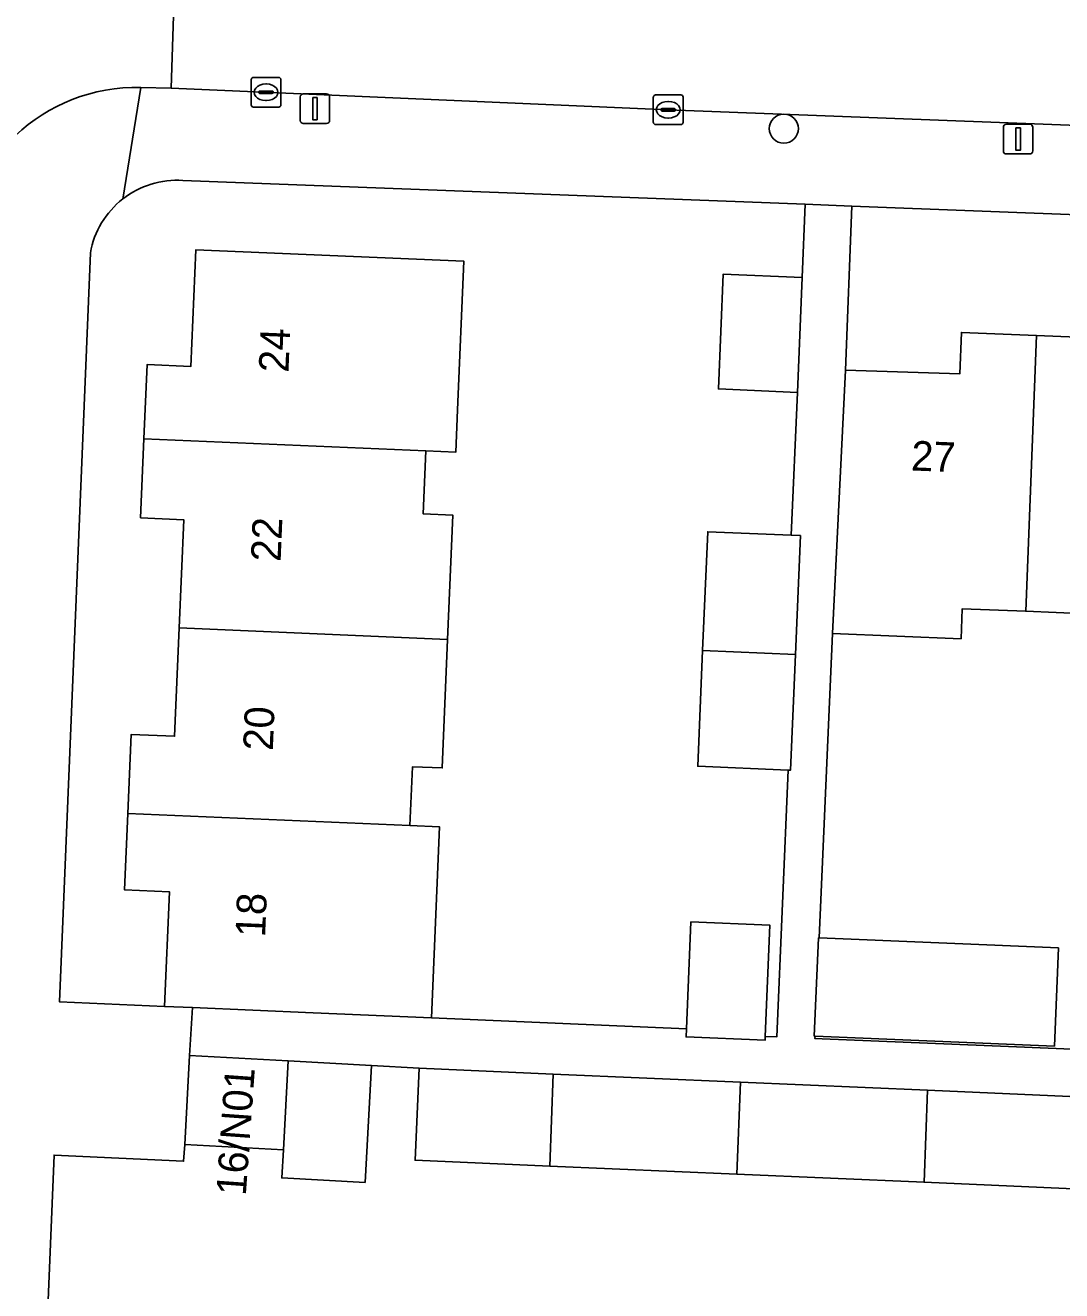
# Model space of a CAD drawing. Extents: x 160732 to 162107, y 387428 to 388479.
# Drawn here: x 161267.54 to 161302.41, y 387574.75 to 387617.33 of the extents above; entities that cross this region are included whole.
import ezdxf

# ---------------------------------------------------------------- set-up
doc = ezdxf.new("R2010")
doc.units = 0
for name, color, linetype in [('IMGEO_Boom', 7, 'Continuous'), ('IMGEO_Erf', 7, 'Continuous'), ('IMGEO_Kolk', 7, 'Continuous'), ('IMGEO_Lichtmast', 7, 'Continuous'), ('IMGEO_Pand', 7, 'Continuous'), ('IMGEO_Pand_nummerreeks', 7, 'Continuous'), ('IMGEO_Rijbaan_lokaal_open', 7, 'Continuous'), ('IMGEO_Voetpad_open', 7, 'Continuous')]:
    doc.layers.add(name, color=color, linetype=linetype)

msp = doc.modelspace()

# ---------------------------------------------------------------- linework, layer by layer
at = {"layer": 'IMGEO_Boom'}
msp.add_circle((161293.062, 387613.849), 0.489, dxfattribs=at)
at = {"layer": 'IMGEO_Erf'}
for points in [[(161293.213, 387592.265), (161290.164, 387592.396), (161290.33, 387596.291), (161290.502, 387600.289), (161293.313, 387600.169), (161293.518, 387604.977), (161290.86, 387605.09), (161291.025, 387608.958), (161293.683, 387608.845), (161293.778, 387611.304), (161272.842, 387612.109)], [(161350.027, 387609.14), (161295.346, 387611.244), (161295.134, 387605.725), (161298.979, 387605.598), (161299.035, 387606.991), (161301.569, 387606.89), (161304.303, 387606.782)], [(161269.729, 387609.67), (161268.695, 387584.47), (161272.229, 387584.319), (161272.394, 387588.17), (161270.882, 387588.235), (161270.992, 387590.81), (161271.106, 387593.468), (161272.562, 387593.406), (161272.718, 387597.051), (161272.873, 387600.693), (161271.416, 387600.756), (161271.53, 387603.417), (161271.636, 387605.91), (161273.114, 387605.847), (161273.282, 387609.775), (161282.296, 387609.389), (161282.082, 387604.394), (161282.021, 387602.964), (161281.021, 387603.007), (161280.93, 387600.886), (161281.93, 387600.843), (161281.751, 387596.661), (161281.567, 387592.341), (161280.568, 387592.383), (161280.483, 387590.4), (161281.482, 387590.357), (161281.207, 387583.935), (161289.783, 387583.569), (161289.936, 387587.161), (161292.594, 387587.048), (161292.435, 387583.31), (161292.825, 387583.294), (161293.213, 387592.265)], [(161303.248, 387597.53), (161301.2, 387597.613), (161299.067, 387597.699), (161299.026, 387596.69), (161294.699, 387596.865), (161294.256, 387586.623), (161302.303, 387586.286), (161302.165, 387582.982), (161294.114, 387583.32), (161294.11, 387583.238), (161294.347, 387583.228), (161300.618, 387582.965), (161303.023, 387582.864)], [(161304.079, 387578.129), (161297.782, 387578.401), (161291.483, 387578.673), (161285.186, 387578.945), (161280.657, 387579.141), (161280.791, 387582.236), (161279.188, 387582.334), (161278.975, 387578.398), (161276.171, 387578.55), (161276.222, 387579.491), (161272.905, 387579.671), (161272.863, 387579.112), (161268.51, 387579.316), (161267.578, 387556.812)]]:
    msp.add_lwpolyline(points, dxfattribs=at)
for centre, radius, start, end in [((161272.657, 387609.136), 2.979, 86.4334, 128.0388), ((161272.653, 387609.143), 2.972, 128.0717, 169.7779)]:
    msp.add_arc(centre, radius, start, end, dxfattribs=at)
at = {"layer": 'IMGEO_Kolk'}
for p, q in [((161275.215, 387615.572), (161276.067, 387615.572)), ((161275.14, 387614.646), (161275.14, 387615.498)), ((161275.442, 387615.115), (161275.84, 387615.115)), ((161275.628, 387615.352), (161275.653, 387615.352)), ((161276.141, 387615.498), (161276.141, 387614.646)), ((161275.399, 387615.066), (161275.399, 387615.078)), ((161275.837, 387615.029), (161275.439, 387615.029)), ((161275.651, 387614.792), (161275.626, 387614.792)), ((161275.883, 387615.078), (161275.883, 387615.066)), ((161288.671, 387614.058), (161288.671, 387614.91)), ((161288.746, 387614.984), (161289.598, 387614.984)), ((161289.159, 387614.764), (161289.184, 387614.764)), ((161289.672, 387614.91), (161289.672, 387614.058)), ((161276.067, 387614.572), (161275.215, 387614.572)), ((161288.93, 387614.478), (161288.93, 387614.49)), ((161289.368, 387614.441), (161288.97, 387614.441)), ((161288.973, 387614.527), (161289.371, 387614.527)), ((161289.414, 387614.49), (161289.414, 387614.478)), ((161289.598, 387613.984), (161288.746, 387613.984)), ((161289.182, 387614.204), (161289.157, 387614.204))]:
    msp.add_line(p, q, dxfattribs=at)
for points in [[(161275.215, 387615.572), (161276.067, 387615.572)], [(161275.14, 387614.646), (161275.14, 387615.498)], [(161276.141, 387615.498), (161276.141, 387614.646)], [(161288.671, 387614.058), (161288.671, 387614.91)], [(161288.746, 387614.984), (161289.598, 387614.984)], [(161289.672, 387614.91), (161289.672, 387614.058)], [(161276.067, 387614.572), (161275.215, 387614.572)], [(161289.598, 387613.984), (161288.746, 387613.984)]]:
    msp.add_lwpolyline(points, dxfattribs=at)
for centre, radius, start, end in [((161275.217, 387615.496), 0.0765, 91.552, 178.448), ((161275.217, 387615.496), 0.0765, 91.552, 178.448), ((161276.065, 387615.496), 0.0765, 1.552, 88.448), ((161276.065, 387615.496), 0.0765, 1.552, 88.448), ((161275.439, 387615.075), 0.0403, 85.8775, 175.7526), ((161275.844, 387615.077), 0.0386, 1.7309, 96.639), ((161275.436, 387615.065), 0.0366, 178.938, 274.7102), ((161275.84, 387615.072), 0.043, 264.8664, 352.4533), ((161288.748, 387614.908), 0.0765, 91.552, 178.448), ((161288.748, 387614.908), 0.0765, 91.552, 178.448), ((161289.596, 387614.908), 0.0765, 1.552, 88.448), ((161289.596, 387614.908), 0.0765, 1.552, 88.448), ((161275.217, 387614.648), 0.0765, 181.552, 268.448), ((161275.217, 387614.648), 0.0765, 181.552, 268.448), ((161276.065, 387614.648), 0.0765, 271.552, 358.448), ((161276.065, 387614.648), 0.0765, 271.552, 358.448), ((161288.97, 387614.487), 0.0403, 85.8775, 175.7526), ((161288.967, 387614.477), 0.0366, 178.938, 274.7102), ((161289.371, 387614.484), 0.043, 264.8664, 352.4533), ((161289.375, 387614.489), 0.0386, 1.7309, 96.639), ((161288.748, 387614.06), 0.0765, 181.552, 268.448), ((161288.748, 387614.06), 0.0765, 181.552, 268.448), ((161289.596, 387614.06), 0.0765, 271.552, 358.448), ((161289.596, 387614.06), 0.0765, 271.552, 358.448)]:
    msp.add_arc(centre, radius, start, end, dxfattribs=at)
for centre, major_axis, ratio, start_param, end_param in [((161275.627, 387615.072), (-0.387, 0.002), 0.722429, 4.712389, 7.853982), ((161275.652, 387615.072), (-0.39, 0.002), 0.717154, 1.570796, 4.712389), ((161289.158, 387614.484), (-0.387, 0.002), 0.722429, 4.712389, 7.853982), ((161289.183, 387614.484), (-0.39, 0.002), 0.717154, 1.570796, 4.712389)]:
    msp.add_ellipse(centre, major_axis=major_axis, ratio=ratio, start_param=start_param, end_param=end_param, dxfattribs=at)
at = {"layer": 'IMGEO_Lichtmast'}
for p, q in [((161276.789, 387614.121), (161276.789, 387614.921)), ((161276.789, 387614.921), (161276.789, 387614.121)), ((161276.889, 387615.021), (161277.679, 387615.021)), ((161277.679, 387615.021), (161276.889, 387615.021)), ((161277.779, 387614.921), (161277.779, 387614.121)), ((161277.779, 387614.121), (161277.779, 387614.921)), ((161277.679, 387614.021), (161276.889, 387614.021)), ((161276.889, 387614.021), (161277.679, 387614.021)), ((161300.45, 387613.099), (161300.45, 387613.899)), ((161300.45, 387613.899), (161300.45, 387613.099)), ((161300.55, 387613.999), (161301.34, 387613.999)), ((161301.34, 387613.999), (161300.55, 387613.999)), ((161301.44, 387613.899), (161301.44, 387613.099)), ((161301.44, 387613.099), (161301.44, 387613.899)), ((161301.34, 387612.999), (161300.55, 387612.999)), ((161300.55, 387612.999), (161301.34, 387612.999))]:
    msp.add_line(p, q, dxfattribs=at)
for points in [[(161277.209, 387614.896), (161277.359, 387614.896), (161277.359, 387614.146), (161277.209, 387614.146), (161277.209, 387614.896)], [(161300.87, 387613.874), (161301.02, 387613.874), (161301.02, 387613.124), (161300.87, 387613.124), (161300.87, 387613.874)]]:
    msp.add_lwpolyline(points, dxfattribs=at)
for centre, start, end in [((161276.889, 387614.921), 90, 180), ((161276.889, 387614.921), 90, 180), ((161277.679, 387614.921), 0, 90), ((161277.679, 387614.921), 360, 90), ((161276.889, 387614.121), 180, 270), ((161276.889, 387614.121), 180, 270), ((161277.679, 387614.121), 270, 0), ((161277.679, 387614.121), 270, 0), ((161300.55, 387613.899), 90, 180), ((161300.55, 387613.899), 90, 180), ((161301.34, 387613.899), 0, 90), ((161301.34, 387613.899), 360, 90), ((161300.55, 387613.099), 180, 270), ((161300.55, 387613.099), 180, 270), ((161301.34, 387613.099), 270, 0), ((161301.34, 387613.099), 270, 0)]:
    msp.add_arc(centre, 0.1, start, end, dxfattribs=at)
at = {"layer": 'IMGEO_Pand'}
for points in [[(161282.296, 387609.389), (161273.282, 387609.775), (161273.114, 387605.847), (161271.636, 387605.91), (161271.53, 387603.417), (161281.021, 387603.007), (161282.021, 387602.964), (161282.082, 387604.394)], [(161293.683, 387608.845), (161291.025, 387608.958), (161290.86, 387605.09), (161293.518, 387604.977)], [(161301.569, 387606.89), (161299.035, 387606.991), (161298.979, 387605.598), (161295.134, 387605.725), (161294.889, 387600.732), (161294.699, 387596.865), (161299.026, 387596.69), (161299.067, 387597.699), (161301.2, 387597.613)], [(161307.807, 387605.189), (161304.245, 387605.331), (161304.303, 387606.782), (161301.569, 387606.89), (161301.2, 387597.613), (161303.248, 387597.53), (161303.206, 387596.519), (161307.455, 387596.343)], [(161281.021, 387603.007), (161271.53, 387603.417), (161271.416, 387600.756), (161272.873, 387600.693), (161272.718, 387597.051), (161281.751, 387596.661), (161281.93, 387600.843), (161280.93, 387600.886)], [(161293.313, 387600.169), (161290.502, 387600.289), (161290.33, 387596.291), (161293.45, 387596.156), (161293.621, 387600.156)], [(161281.751, 387596.661), (161272.718, 387597.051), (161272.562, 387593.406), (161271.106, 387593.468), (161270.992, 387590.81), (161280.483, 387590.4), (161280.568, 387592.383), (161281.567, 387592.341)], [(161293.45, 387596.156), (161290.33, 387596.291), (161290.164, 387592.396), (161293.213, 387592.265), (161293.283, 387592.262)], [(161281.482, 387590.357), (161280.483, 387590.4), (161270.992, 387590.81), (161270.882, 387588.235), (161272.394, 387588.17), (161272.229, 387584.319), (161273.16, 387584.279), (161277.225, 387584.105), (161281.207, 387583.935)], [(161292.594, 387587.048), (161289.936, 387587.161), (161289.783, 387583.569), (161289.771, 387583.293), (161292.429, 387583.18), (161292.435, 387583.31)], [(161294.256, 387586.623), (161294.224, 387586.624), (161294.085, 387583.321), (161294.114, 387583.32), (161302.165, 387582.982), (161302.303, 387586.286)], [(161273.067, 387582.666), (161272.905, 387579.671), (161276.222, 387579.491), (161276.384, 387582.486)], [(161276.222, 387579.491), (161276.171, 387578.55), (161278.975, 387578.398), (161279.188, 387582.334), (161276.384, 387582.486)], [(161285.302, 387582.042), (161280.791, 387582.236), (161280.657, 387579.141), (161285.186, 387578.945)], [(161291.6, 387581.769), (161285.302, 387582.042), (161285.186, 387578.945), (161291.483, 387578.673)], [(161297.898, 387581.497), (161291.6, 387581.769), (161291.483, 387578.673), (161297.782, 387578.401)], [(161304.196, 387581.225), (161297.898, 387581.497), (161297.782, 387578.401), (161304.079, 387578.129)]]:
    msp.add_lwpolyline(points, close=True, dxfattribs=at)
at = {"layer": 'IMGEO_Rijbaan_lokaal_open'}
msp.add_lwpolyline([(161271.428, 387615.232), (161272.446, 387615.211), (161272.605, 387620.102)], dxfattribs=at)
msp.add_lwpolyline([(161273.653, 387620.056), (161272.605, 387620.102), (161272.446, 387615.211), (161289.172, 387614.484), (161312.936, 387613.577), (161343.203, 387612.394), (161343.386, 387617.292)], close=True, dxfattribs=at)
msp.add_arc((161271.275, 387609.313), 5.921, 88.5203, 178.1993, dxfattribs=at)
at = {"layer": 'IMGEO_Voetpad_open'}
for points in [[(161422.811, 387609.126), (161411.375, 387609.658), (161407.95, 387609.79), (161356.144, 387611.896), (161356.112, 387610.696), (161347.841, 387611.016), (161347.913, 387612.202), (161346.661, 387612.253), (161343.203, 387612.394), (161312.936, 387613.577), (161289.172, 387614.484), (161272.446, 387615.211), (161271.428, 387615.232), (161270.821, 387611.482)], [(161270.821, 387611.482), (161271.428, 387615.232)], [(161272.842, 387612.109), (161293.778, 387611.304), (161295.346, 387611.244), (161350.027, 387609.14), (161354.703, 387608.945), (161354.697, 387608.799), (161396.894, 387607.128), (161398.295, 387607.073), (161409.384, 387606.634), (161415.333, 387606.399), (161420.803, 387606.202)], [(161303.023, 387582.864), (161300.618, 387582.965), (161294.347, 387583.228), (161294.11, 387583.238), (161294.114, 387583.32), (161294.085, 387583.321), (161294.224, 387586.624), (161294.256, 387586.623), (161294.699, 387596.865), (161294.889, 387600.732), (161295.134, 387605.725), (161295.346, 387611.244), (161293.778, 387611.304), (161293.683, 387608.845), (161293.518, 387604.977), (161293.313, 387600.169), (161293.621, 387600.156), (161293.45, 387596.156), (161293.283, 387592.262), (161293.213, 387592.265), (161292.825, 387583.294), (161292.435, 387583.31), (161292.429, 387583.18), (161289.771, 387583.293), (161289.783, 387583.569), (161281.207, 387583.935), (161277.225, 387584.105), (161273.16, 387584.279), (161273.067, 387582.666), (161276.384, 387582.486), (161279.188, 387582.334), (161280.791, 387582.236), (161285.302, 387582.042), (161291.6, 387581.769), (161297.898, 387581.497), (161304.196, 387581.225)], [(161268.51, 387579.316), (161272.863, 387579.112), (161272.905, 387579.671), (161273.067, 387582.666), (161273.16, 387584.279), (161272.229, 387584.319), (161268.695, 387584.47), (161269.729, 387609.67)], [(161267.578, 387556.812), (161268.51, 387579.316)]]:
    msp.add_lwpolyline(points, dxfattribs=at)
for centre, radius, start, end in [((161271.275, 387609.313), 5.921, 88.5203, 178.1993), ((161272.657, 387609.136), 2.979, 86.4334, 128.0388), ((161272.653, 387609.143), 2.972, 128.0717, 169.7779)]:
    msp.add_arc(centre, radius, start, end, dxfattribs=at)

# ---------------------------------------------------------------- texts
at = {"layer": 'IMGEO_Pand_nummerreeks'}
for s, rotation, p in [('24', 87.6339, (161276.393, 387605.632)), ('27', 357.6165, (161297.332, 387602.351)), ('22', 87.6339, (161276.13, 387599.265)), ('20', 87.6339, (161275.867, 387592.907)), ('18', 87.6339, (161275.607, 387586.634)), ('16/N01', 85.9144, (161274.958, 387577.932))]:
    msp.add_text(s, height=1, rotation=rotation, dxfattribs=at).set_placement(p)

doc.saveas('drawing.dxf')
